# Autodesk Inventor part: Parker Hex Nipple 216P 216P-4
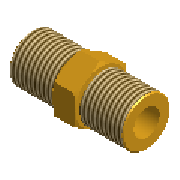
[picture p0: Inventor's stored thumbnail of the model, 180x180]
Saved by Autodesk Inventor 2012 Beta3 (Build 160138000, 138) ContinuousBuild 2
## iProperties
Created: 2010-12
Part Number: Parker Hex Nipple 216P 216P-4
Material: Brass, Soft Yellow
Description: Hex Nipple
Document SubType Name: Modeling
Standard: Parker
Designer: Beta-8540w
Manufacturer: Parker
Language: en-US
Size Designation: 216P-4
Categories: <MemberInstance><Categories><Category DisplayName="Tube &amp; Pipe" InternalName="4347fa0f-2144-441d-94cd-e3e15c92b736" Mnemonic="TUBEANDPIPE"><CategoryParamete
Density: 8.47 g/cm^3
NAME: PIPING: Parker Hex Nipple 216P
DATA: <meta><inlinegroups number="1" deflen="2.4638"></inlinegroups><connections number="2"></connections><angles><a>3.14159265358979</a></angles></meta>
IsCustomPart: 0
Author: Beta-8540w
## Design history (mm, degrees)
sketch "Sketch1"
  geometry: L1 (8.249, 0)-(4.124, -7.144); L2 (4.124, -7.144)-(-4.124, -7.144); L3 (-4.124, -7.144)-(-8.249, 0); L4 (-8.249, 0)-(-4.124, 7.144); L5 (-4.124, 7.144)-(4.124, 7.144); L6 (4.124, 7.144)-(8.249, 0); 2 further points
  constraints: 12 end point, 1 coincident, 1 horizontal, 11 other
  dimensions: "d0" = 14.2875 distance between parallel lines of L5 L2 (= C_HEX)
extrude "Extrusion1" new body sketch "Sketch1" stored distance "d1" = 7.0104 (= 0.2 x L); taper "d2" = 0 deg
sketch "Sketch2"
  geometry: L1 (0, 0)-(7.075, 0); L2 (-3.505, 0)-(-17.526, 0); L3 (-3.505, 0)-(-3.505, 6.072); L4 (-3.505, 6.072)-(-4.206, 6.072); L5 (-4.206, 6.072)-(-4.206, 6.858); L6 (-4.206, 6.858)-(-17.526, 6.858); L7 (-17.526, 6.858)-(-17.526, 0); L8 (-22.446, 0)-(11.995, 0) reference; L9 (-3.505, 4.124)-(-3.505, -4.124) reference
  constraints: 14 end point, 3 parallel, 2 collinear, 2 perpendicular, 2 point on line
  dimensions: "d3" = 14.0208 distance of L2.start L2.end (= 0.4 x L); "d6" = 13.31976 distance from line of L4.end L7 (= 0.38 x L); "d32" = 13.716 diameter of L6 L1; "d33" = 12.14437 diameter of L4 L1 (= 0.85 x C_HEX)
revolve "Revolution1" sketch "Sketch2" stored, may be unused: angle "d7" = 90 deg
mirror "Mirror1"
sketch "Sketch5"
  geometry: L1 (3.505, -7.144)-(-3.505, -7.144) reference; L2 (-3.505, -7.144)-(-3.505, -14.287); L3 (-3.505, -7.144)-(-0.174, -14.287); L4 (-3.505, -14.287)-(-0.174, -14.287); L5 (0, -15.716)-(0, -5.715) reference; L6 (4.907, 0)-(-4.907, 0) reference
  constraints: 6 end point, 2 perpendicular
  dimensions: "d15" = 7.14375 distance of L1.end L2.end (= 0.5 x C_HEX); "d38" = 25 deg angle of L2 L3
revolve "Revolution4" sketch "Sketch5" stored, may be unused: angle "d16" = 90 deg
mirror "Mirror2"
chamfer "Chamfer1" distance "d17" = 0.28575 (= 0.02 x C_HEX); stored, may be unused: second distance "d18" = 3.175, angle "d19" = 45 deg
hole "Hole1" diameter "d22" = 7.9756 (= D); stored, may be unused: countersink angle "d26" = 82 deg, drill point angle "d28" = 118 deg; dims "d20" = 25.4, "d21" = 25.4, "d23" = 12.7, "d24" = 9.525, "d25" = 6.35, "d27" = 19.05
thread "Thread1" dims "d34" = 25.4, "d35" = 0
thread "Thread2" dims "d36" = 25.4, "d37" = 0
workaxis "Work Axis1"
workpoint "Work Point1"
workaxis "Work Axis2"
workpoint "Work Point2"
workaxis "Work Axis3"
workaxis "Work Axis4"
workpoint "Work Point3"
workpoint "Work Point4"
body "Solid1"
other parameters: "C_HEX" = 14.2875 [user parameter; used in 4 equation terms], "L" = 35.052 [user parameter; used in 3 equation terms], "D" = 7.9756 [user parameter; used in 1 equation term], "ND1" = 9.652 [user parameter], "Parker_No" = 12.345 [user parameter]
